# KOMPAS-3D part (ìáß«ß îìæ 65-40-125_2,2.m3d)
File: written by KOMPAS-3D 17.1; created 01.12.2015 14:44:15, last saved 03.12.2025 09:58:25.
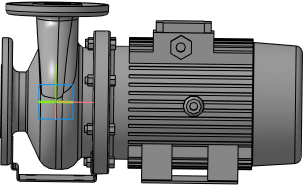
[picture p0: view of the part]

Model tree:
1. Операция без истории:5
